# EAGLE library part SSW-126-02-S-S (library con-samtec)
THROUGH-HOLE .025" SQ POST SOCKET Source: Samtec SSW.pdf
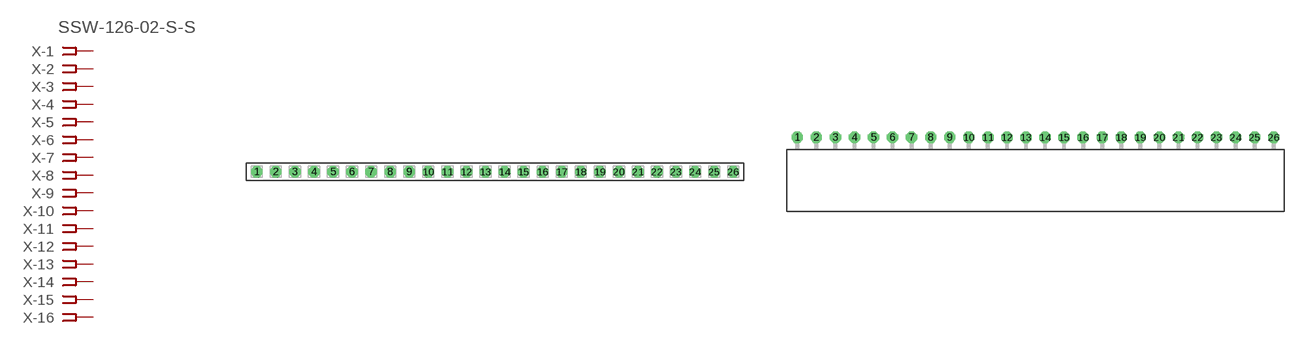
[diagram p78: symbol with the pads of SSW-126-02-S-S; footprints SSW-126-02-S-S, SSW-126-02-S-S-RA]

Designator prefix X; gates -1=FPINV -2=FPIN -3=FPIN -4=FPIN -5=FPIN -6=FPIN -7=FPIN -8=FPIN -9=FPIN -10=FPIN -11=FPIN -12=FPIN -13=FPIN -14=FPIN -15=FPIN -16=FPIN -17=FPIN -18=FPIN -19=FPIN -20=FPIN -21=FPIN -22=FPIN -23=FPIN -24=FPIN -25=FPIN -26=FPIN

## SSW-126-02-S-S (MPN: SSW-126-02-S-S; OC_FARNELL: unknown; OC_NEWARK: 11P9742)  [SSW-126-02-S-S]
1  -1:1  pas
2  -2:1  pas
3  -3:1  pas
4  -4:1  pas
5  -5:1  pas
6  -6:1  pas
7  -7:1  pas
8  -8:1  pas
9  -9:1  pas
10  -10:1  pas
11  -11:1  pas
12  -12:1  pas
13  -13:1  pas
14  -14:1  pas
15  -15:1  pas
16  -16:1  pas
17  -17:1  pas
18  -18:1  pas
19  -19:1  pas
20  -20:1  pas
21  -21:1  pas
22  -22:1  pas
23  -23:1  pas
24  -24:1  pas
25  -25:1  pas
26  -26:1  pas

## SSW-126-02-S-S-RA (MPN: SSW-126-02-S-S-RA; OC_FARNELL: unknown; OC_NEWARK: 11P9743)  [SSW-126-02-S-S-RA]
Pads as for SSW-126-02-S-S

## Footprint SSW-126-02-S-S (pad centres in mm)
THROUGH-HOLE .025" SQ POST SOCKET Source: Samtec SSW.pdf
drill 1 pad 1.5 octagon: 1 -31.75,0; 2 -29.21,0; 3 -26.67,0; 4 -24.13,0; 5 -21.59,0; 6 -19.05,0; 7 -16.51,0; 8 -13.97,0; 9 -11.43,0; 10 -8.89,0; 11 -6.35,0; 12 -3.81,0; 13 -1.27,0; 14 1.27,0; 15 3.81,0; 16 6.35,0; 17 8.89,0; 18 11.43,0; 19 13.97,0; 20 16.51,0; 21 19.05,0; 22 21.59,0; 23 24.13,0; 24 26.67,0; 25 29.21,0; 26 31.75,0

## Footprint SSW-126-02-S-S-RA (pad centres in mm)
THROUGH-HOLE .025" SQ POST SOCKET Source: Samtec SSW.pdf
drill 1 pad 1.5 octagon: 1 -31.75,1.524; 2 -29.21,1.524; 3 -26.67,1.524; 4 -24.13,1.524; 5 -21.59,1.524; 6 -19.05,1.524; 7 -16.51,1.524; 8 -13.97,1.524; 9 -11.43,1.524; 10 -8.89,1.524; 11 -6.35,1.524; 12 -3.81,1.524; 13 -1.27,1.524; 14 1.27,1.524; 15 3.81,1.524; 16 6.35,1.524; 17 8.89,1.524; 18 11.43,1.524; 19 13.97,1.524; 20 16.51,1.524; 21 19.05,1.524; 22 21.59,1.524; 23 24.13,1.524; 24 26.67,1.524; 25 29.21,1.524; 26 31.75,1.524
